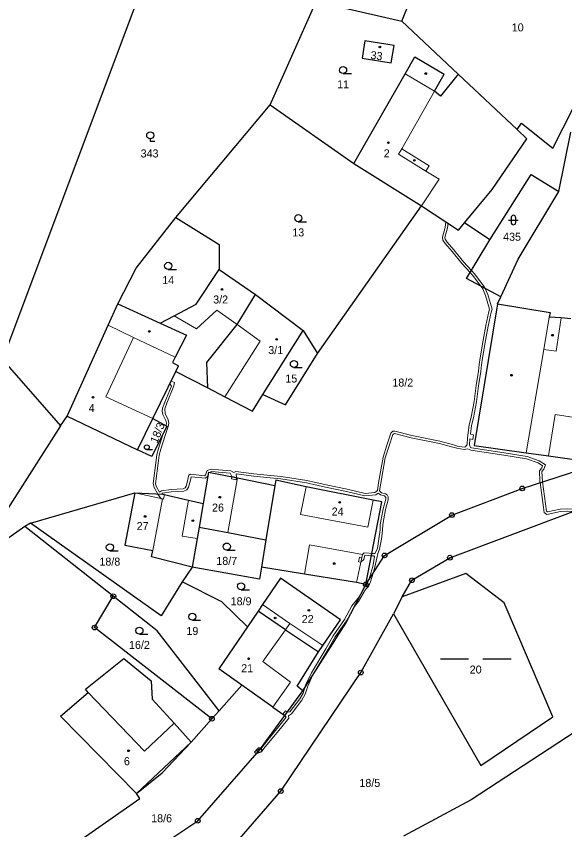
# Model space of a CAD drawing. Extents: x -791548 to -789311, y -1142631 to -1140855.
# Drawn here: x -790444.3 to -790327.9, y -1142288.4 to -1142115.7 of the extents above; entities that cross this region are included whole.
import ezdxf
from ezdxf.enums import TextEntityAlignment as Align

# ---------------------------------------------------------------- set-up
doc = ezdxf.new("R2010")
doc.units = 0
doc.header["$LTSCALE"] = 0.68
for name, color, linetype, lineweight in [('1', 7, 'Continuous', 25), ('13', 7, 'Continuous', 13), ('3', 7, 'Continuous', 25), ('4', 7, 'Continuous', 13), ('5', 7, 'Continuous', 25), ('8', 7, 'Continuous', 25)]:
    doc.layers.add(name, color=color, linetype=linetype, lineweight=lineweight)
doc.layers.add('2', color=7, linetype='Continuous')

msp = doc.modelspace()

# ---------------------------------------------------------------- linework, layer by layer
at = {"layer": '1'}
for p, q in [((-790415.68, -1142104.15), (-790447.27, -1142188.54)), ((-790330.46, -1142143.68), (-790314.29, -1142111.65)), ((-790390.45, -1142134.47), (-790380.65, -1142112.49)), ((-790380.65, -1142112.49), (-790362.5, -1142116.7)), ((-790362.5, -1142116.7), (-790360.74, -1142112.34)), ((-790362.5, -1142116.7), (-790350.55, -1142127.95)), ((-790370.32, -1142120.88), (-790370.91, -1142124.53)), ((-790364.14, -1142121.88), (-790370.32, -1142120.88)), ((-790364.73, -1142125.53), (-790364.14, -1142121.88)), ((-790361.79, -1142127.86), (-790359.72, -1142124.25)), ((-790359.72, -1142124.25), (-790353.52, -1142127.92)), ((-790370.91, -1142124.53), (-790364.73, -1142125.53)), ((-790372.68, -1142146.9), (-790361.79, -1142127.86)), ((-790355.58, -1142131.57), (-790353.52, -1142127.92)), ((-790350.55, -1142127.95), (-790354.27, -1142132.64)), ((-790350.55, -1142127.95), (-790338.04, -1142139.73)), ((-790354.27, -1142132.64), (-790355.58, -1142131.57)), ((-790410.46, -1142158.37), (-790390.45, -1142134.47)), ((-790390.45, -1142134.47), (-790372.68, -1142146.9)), ((-790338.04, -1142139.73), (-790337.12, -1142138.36)), ((-790335.94, -1142141.69), (-790338.04, -1142139.73)), ((-790337.12, -1142138.36), (-790330.46, -1142143.68)), ((-790329.14, -1142152.86), (-790326.62, -1142140.29)), ((-790343.35, -1142152.44), (-790335.94, -1142141.69)), ((-790372.68, -1142146.9), (-790358.3, -1142155.94)), ((-790343.85, -1142163.15), (-790335.03, -1142149.26)), ((-790335.03, -1142149.26), (-790329.14, -1142152.86)), ((-790349.2, -1142159.55), (-790343.35, -1142152.44)), ((-790337.78, -1142167.2), (-790329.14, -1142152.86)), ((-790380.41, -1142187.28), (-790358.3, -1142155.94)), ((-790358.3, -1142155.94), (-790350.46, -1142161.08)), ((-790418.91, -1142169.15), (-790410.46, -1142158.37)), ((-790410.46, -1142158.37), (-790401.23, -1142164.11)), ((-790350.46, -1142161.08), (-790349.2, -1142159.55)), ((-790343.85, -1142163.15), (-790349.2, -1142159.55)), ((-790348.76, -1142171.34), (-790343.85, -1142163.15)), ((-790401.23, -1142164.11), (-790401.29, -1142169.44)), ((-790341.49, -1142175.23), (-790337.78, -1142167.2)), ((-790422.8, -1142176.69), (-790418.91, -1142169.15)), ((-790406.11, -1142176.79), (-790401.29, -1142169.44)), ((-790401.29, -1142169.44), (-790393.58, -1142174.73)), ((-790341.49, -1142175.23), (-790348.76, -1142171.34)), ((-790397.42, -1142181.07), (-790393.58, -1142174.73)), ((-790393.58, -1142174.73), (-790383.43, -1142182.39)), ((-790342.17, -1142176.71), (-790341.49, -1142175.23)), ((-790424.85, -1142181.26), (-790422.8, -1142176.69)), ((-790422.8, -1142176.69), (-790413.8, -1142180.83)), ((-790410.81, -1142179.26), (-790406.11, -1142176.79)), ((-790342.17, -1142176.71), (-790347.13, -1142206.82)), ((-790342.17, -1142176.71), (-790331.02, -1142178.55)), ((-790413.8, -1142180.83), (-790410.81, -1142179.26)), ((-790331.02, -1142178.55), (-790331.19, -1142179.52)), ((-790328.69, -1142179.71), (-790331.19, -1142179.52)), ((-790433.54, -1142200.57), (-790424.85, -1142181.26)), ((-790413.8, -1142180.83), (-790408.2, -1142183.4)), ((-790403.88, -1142189.18), (-790397.42, -1142181.07)), ((-790326.63, -1142179.87), (-790328.69, -1142179.71)), ((-790391.97, -1142195.94), (-790383.43, -1142182.39)), ((-790383.43, -1142182.39), (-790380.41, -1142187.28)), ((-790408.2, -1142183.4), (-790410.6, -1142188.02)), ((-790410.6, -1142188.02), (-790411.2, -1142189.17)), ((-790387.15, -1142198.15), (-790380.41, -1142187.28)), ((-790447.27, -1142188.54), (-790434.91, -1142202.65)), ((-790411.2, -1142189.17), (-790409.88, -1142189.89)), ((-790410.45, -1142191.06), (-790409.88, -1142189.89)), ((-790403.7, -1142194.56), (-790403.88, -1142189.18)), ((-790415.35, -1142201.03), (-790410.45, -1142191.06)), ((-790410.45, -1142191.06), (-790403.7, -1142194.56)), ((-790403.7, -1142194.56), (-790400.06, -1142196.44)), ((-790400.06, -1142196.44), (-790394.2, -1142199.48)), ((-790394.2, -1142199.48), (-790391.97, -1142195.94)), ((-790391.97, -1142195.94), (-790387.15, -1142198.15)), ((-790434.91, -1142202.65), (-790433.54, -1142200.57)), ((-790433.54, -1142200.57), (-790418.62, -1142207.68)), ((-790418.62, -1142207.68), (-790415.35, -1142201.03)), ((-790415.35, -1142201.03), (-790412.38, -1142202.69)), ((-790434.91, -1142202.65), (-790447.12, -1142221.74)), ((-790412.38, -1142202.69), (-790415.55, -1142209.15)), ((-790347.13, -1142206.82), (-790336.11, -1142208.37)), ((-790415.55, -1142209.15), (-790418.62, -1142207.68)), ((-790336.11, -1142208.37), (-790331.39, -1142209)), ((-790331.39, -1142209), (-790297.38, -1142213.8)), ((-790336.95, -1142215.9), (-790324.53, -1142211.91)), ((-790403.5, -1142212.48), (-790404.64, -1142219.08)), ((-790403.5, -1142212.48), (-790397.37, -1142213.63)), ((-790397.37, -1142213.63), (-790389.44, -1142215.31)), ((-790389.44, -1142215.31), (-790391.33, -1142226.82)), ((-790389.23, -1142214.18), (-790389.44, -1142215.31)), ((-790382.81, -1142215.54), (-790389.23, -1142214.18)), ((-790368.61, -1142218.37), (-790382.81, -1142215.54)), ((-790441.28, -1142223.26), (-790419.19, -1142216.86)), ((-790419.19, -1142216.86), (-790421.25, -1142227.97)), ((-790419.19, -1142216.86), (-790413.19, -1142217.16)), ((-790413.19, -1142217.16), (-790407.76, -1142218.38)), ((-790351.87, -1142221.56), (-790336.95, -1142215.9)), ((-790370.14, -1142236.3), (-790366.75, -1142218.74)), ((-790366.75, -1142218.74), (-790368.61, -1142218.37)), ((-790352.29, -1142230.61), (-790326.11, -1142220.77)), ((-790366.17, -1142230.14), (-790351.87, -1142221.56)), ((-790442.51, -1142223.96), (-790460.61, -1142236.7)), ((-790441.28, -1142223.26), (-790442.51, -1142223.96)), ((-790423.73, -1142238.79), (-790442.51, -1142223.96)), ((-790413.55, -1142242.99), (-790441.28, -1142223.26)), ((-790405.52, -1142224.14), (-790405.94, -1142226.57)), ((-790405.52, -1142224.14), (-790399.43, -1142225.29)), ((-790399.43, -1142225.29), (-790391.33, -1142226.82)), ((-790405.94, -1142226.57), (-790406.98, -1142232.61)), ((-790391.33, -1142226.82), (-790392.28, -1142232.62)), ((-790421.25, -1142227.97), (-790415.36, -1142229.07)), ((-790415.61, -1142230.43), (-790415.36, -1142229.07)), ((-790406.98, -1142232.61), (-790415.61, -1142230.43)), ((-790370.14, -1142236.3), (-790366.17, -1142230.14)), ((-790360.35, -1142235.41), (-790352.29, -1142230.61)), ((-790406.98, -1142232.61), (-790409.14, -1142235.72)), ((-790392.72, -1142235.14), (-790406.98, -1142232.61)), ((-790392.28, -1142232.62), (-790392.72, -1142235.14)), ((-790383.13, -1142234.11), (-790392.28, -1142232.62)), ((-790372.09, -1142235.91), (-790383.13, -1142234.11)), ((-790348.92, -1142234), (-790362.42, -1142238.92)), ((-790340.78, -1142240.21), (-790348.92, -1142234)), ((-790409.14, -1142235.72), (-790413.55, -1142242.99)), ((-790400.69, -1142239.95), (-790409.14, -1142235.72)), ((-790388.24, -1142234.94), (-790392.07, -1142240.58)), ((-790375.51, -1142243.78), (-790388.24, -1142234.94)), ((-790374.36, -1142244.52), (-790370.14, -1142236.3)), ((-790370.14, -1142236.3), (-790372.09, -1142235.91)), ((-790362.42, -1142238.92), (-790360.35, -1142235.41)), ((-790427.69, -1142245.45), (-790423.73, -1142238.79)), ((-790414.42, -1142246.14), (-790423.73, -1142238.79)), ((-790395.28, -1142245.29), (-790400.69, -1142239.95)), ((-790362.42, -1142238.92), (-790364.25, -1142242.5)), ((-790392.07, -1142240.58), (-790393, -1142241.95)), ((-790330.43, -1142264.38), (-790340.78, -1142240.21)), ((-790393, -1142241.95), (-790395.28, -1142245.29)), ((-790387.21, -1142245.94), (-790393, -1142241.95)), ((-790371.2, -1142255), (-790364.25, -1142242.5)), ((-790364.25, -1142242.5), (-790345.76, -1142274.76)), ((-790383.5, -1142258.87), (-790374.36, -1142244.52)), ((-790379.28, -1142249.22), (-790375.51, -1142243.78)), ((-790402.79, -1142264.82), (-790427.69, -1142245.45)), ((-790401.26, -1142263.11), (-790414.42, -1142246.14)), ((-790395.28, -1142245.29), (-790401.34, -1142254.22)), ((-790387.21, -1142245.94), (-790380.15, -1142250.62)), ((-790380.15, -1142250.62), (-790379.28, -1142249.22)), ((-790429.63, -1142258.56), (-790421.48, -1142251.99)), ((-790421.48, -1142251.99), (-790415.72, -1142256.74)), ((-790384.72, -1142257.9), (-790380.15, -1142250.62)), ((-790396.42, -1142257.7), (-790401.34, -1142254.22)), ((-790388.19, -1142280.16), (-790371.2, -1142255)), ((-790415.72, -1142256.74), (-790415.45, -1142260.62)), ((-790429.09, -1142259.22), (-790429.63, -1142258.56)), ((-790401.26, -1142263.11), (-790396.42, -1142257.7)), ((-790389.89, -1142262.32), (-790396.42, -1142257.7)), ((-790387.33, -1142264.12), (-790383.5, -1142258.87)), ((-790383.5, -1142258.87), (-790384.72, -1142257.9)), ((-790434.96, -1142264.23), (-790429.09, -1142259.22)), ((-790415.45, -1142260.62), (-790410.82, -1142265.77)), ((-790389.89, -1142262.32), (-790387.33, -1142264.12)), ((-790402.79, -1142264.82), (-790401.26, -1142263.11)), ((-790392.71, -1142271.46), (-790387.33, -1142264.12)), ((-790319.06, -1142263.2), (-790347.8, -1142282.01)), ((-790418.82, -1142280.69), (-790434.96, -1142264.23)), ((-790410.82, -1142265.77), (-790407.22, -1142269.77)), ((-790407.22, -1142269.77), (-790402.79, -1142264.82)), ((-790345.76, -1142274.76), (-790330.43, -1142264.38)), ((-790413.33, -1142276.29), (-790407.22, -1142269.77)), ((-790405.82, -1142286.48), (-790392.71, -1142271.46)), ((-790418.82, -1142280.69), (-790413.33, -1142276.29)), ((-790418.1, -1142281.74), (-790418.82, -1142280.69)), ((-790399.5, -1142293.19), (-790388.19, -1142280.16)), ((-790441.89, -1142298.31), (-790418.1, -1142281.74)), ((-790347.8, -1142282.01), (-790362.11, -1142289.76)), ((-790422.96, -1142297.87), (-790405.82, -1142286.48))]:
    msp.add_line(p, q, dxfattribs=at)
msp.add_lwpolyline([(-790407.76, -1142218.38), (-790404.64, -1142219.08), (-790405.52, -1142224.14)], dxfattribs=at)
at = {"layer": '13'}
for points in [[(-790353.14, -1142159.32), (-790353.32, -1142160.48), (-790353.87, -1142162.57), (-790353.8, -1142163.17), (-790353.3, -1142163.92), (-790351.83, -1142165.6), (-790349.76, -1142168.13), (-790348, -1142170.07), (-790347.73, -1142169.62), (-790349.38, -1142167.81), (-790351.45, -1142165.28), (-790352.9, -1142163.62), (-790353.32, -1142162.99), (-790353.37, -1142162.61), (-790352.82, -1142160.58), (-790352.68, -1142159.62)], [(-790347.73, -1142169.62), (-790348, -1142170.07), (-790347.46, -1142170.66), (-790345.7, -1142172.98), (-790344.8, -1142173.46), (-790344.86, -1142173.32), (-790345.3, -1142172.68), (-790347.08, -1142170.34)], [(-790398.67, -1142213.89), (-790397.69, -1142214.08), (-790397.6, -1142213.59), (-790398.58, -1142213.4)], [(-790332.65, -1142214.52), (-790333.14, -1142214.68), (-790332.28, -1142221), (-790331.71, -1142221.45), (-790328.85, -1142220.82), (-790327.24, -1142220.74), (-790326.11, -1142220.77), (-790319.06, -1142221.21), (-790317.66, -1142221.3), (-790318.89, -1142220.75), (-790321.01, -1142220.53), (-790325.13, -1142220.29), (-790327.24, -1142220.24), (-790328.91, -1142220.32), (-790331.59, -1142220.91), (-790331.82, -1142220.74)], [(-790413.54, -1142218.09), (-790413.3, -1142218.14), (-790413.06, -1142218.19), (-790412.88, -1142217.23), (-790413.19, -1142217.16), (-790414.31, -1142217.1)], [(-790368.96, -1142230.19), (-790368.86, -1142229.69), (-790369.44, -1142229.63), (-790370.51, -1142229.56), (-790370.87, -1142229.91), (-790371.01, -1142230.59), (-790371.5, -1142230.49), (-790371.7, -1142231.47), (-790371.21, -1142231.57), (-790370.54, -1142230.99), (-790370.37, -1142230.09), (-790369.48, -1142230.13)], [(-790368.57, -1142233.87), (-790369.51, -1142235.32), (-790370, -1142236.43), (-790370.46, -1142236.92), (-790371.45, -1142238.85), (-790372.55, -1142241), (-790371.69, -1142239.94), (-790370.23, -1142237.4), (-790369.6, -1142236.75), (-790369.11, -1142235.71)], [(-790383.06, -1142258.18), (-790381.35, -1142255.49), (-790378.2, -1142250.19), (-790376.63, -1142247.43), (-790374.25, -1142244), (-790372.55, -1142241), (-790371.45, -1142238.85), (-790373.08, -1142240.86), (-790374.67, -1142243.74), (-790377.05, -1142247.17), (-790378.64, -1142249.93), (-790381.7, -1142255.06), (-790382.91, -1142257.69)], [(-790381.35, -1142255.49), (-790383.06, -1142258.18), (-790383.44, -1142259.4), (-790384.17, -1142260.55), (-790386.23, -1142263.37), (-790386.81, -1142263.4), (-790387.33, -1142264.12), (-790387.01, -1142264.49), (-790388.66, -1142266.54), (-790390.84, -1142269.19), (-790392.15, -1142270.81), (-790392.71, -1142271.46), (-790393.4, -1142272.25), (-790392.3, -1142271.83), (-790391.75, -1142271.11), (-790390.46, -1142269.51), (-790388.28, -1142266.86), (-790386.49, -1142264.65), (-790386.54, -1142264.18), (-790385.89, -1142263.75), (-790383.75, -1142260.83), (-790382.98, -1142259.62), (-790382.45, -1142257.87)], [(-790387.74, -1142263.83), (-790387.33, -1142264.12), (-790386.81, -1142263.4), (-790387.21, -1142263.11)], [(-790393.12, -1142271.16), (-790393.77, -1142271.92), (-790393.4, -1142272.25), (-790392.71, -1142271.46)]]:
    msp.add_lwpolyline(points, close=True, dxfattribs=at)
for points in [[(-790364.02, -1142204.25), (-790360.51, -1142205.14), (-790354.53, -1142206.36), (-790351.7, -1142207.13), (-790350.82, -1142207.38), (-790349.26, -1142207.67), (-790348.56, -1142207.47), (-790347.85, -1142207.78), (-790340.82, -1142208.84), (-790336.02, -1142209.62), (-790333.54, -1142210.5), (-790332.65, -1142211.1), (-790332.79, -1142211.54), (-790333.27, -1142212.16), (-790333.17, -1142214.44), (-790333.14, -1142214.68), (-790332.65, -1142214.52), (-790332.77, -1142212.32), (-790332.35, -1142211.8), (-790332.01, -1142210.93), (-790333.32, -1142210.04), (-790335.9, -1142209.14), (-790340.74, -1142208.34), (-790347.71, -1142207.3), (-790347.93, -1142207.2), (-790348.13, -1142206.66), (-790348.07, -1142205.39), (-790347.45, -1142205.49), (-790347.29, -1142204.51), (-790347.95, -1142204.4), (-790347.68, -1142202.52), (-790347.28, -1142200.91), (-790346.67, -1142197.54), (-790346.22, -1142194.12), (-790345.74, -1142191.05), (-790345.58, -1142189.68), (-790345.38, -1142188.27), (-790344.74, -1142184.49), (-790344.19, -1142181.44), (-790343.52, -1142178.45), (-790343.32, -1142177.83), (-790344.26, -1142174.75), (-790344.8, -1142173.46), (-790345.7, -1142172.98), (-790345.3, -1142173.56), (-790344.74, -1142174.91), (-790343.86, -1142177.88), (-790344, -1142178.31), (-790344.69, -1142181.34), (-790345.24, -1142184.41), (-790345.88, -1142188.19), (-790346.08, -1142189.62), (-790346.24, -1142190.99), (-790346.72, -1142194.04), (-790347.17, -1142197.46), (-790347.76, -1142200.81), (-790348.18, -1142202.42), (-790348.56, -1142205.13), (-790348.63, -1142206.6), (-790348.95, -1142207.06), (-790349.28, -1142207.15), (-790350.7, -1142206.9), (-790351.56, -1142206.65), (-790354.41, -1142205.88), (-790360.39, -1142204.66), (-790363.98, -1142203.75), (-790364.43, -1142203.78), (-790364.84, -1142204.15), (-790365.67, -1142206.69), (-790366.48, -1142209.28), (-790367.43, -1142214.74), (-790367.69, -1142216.35), (-790368.2, -1142216.76), (-790370.29, -1142216.96), (-790374.13, -1142216.09), (-790378.56, -1142215.17), (-790382.63, -1142214.25), (-790388.08, -1142213.36), (-790390.38, -1142213.16), (-790393.88, -1142212.79), (-790397.76, -1142212.28), (-790398.12, -1142212.53), (-790398.81, -1142212.18), (-790401.4, -1142211.94), (-790402.9, -1142211.8), (-790403.79, -1142212.08), (-790404.13, -1142213.02), (-790404.33, -1142213.21), (-790407.34, -1142212.89), (-790407.7, -1142213.12), (-790407.83, -1142213.59), (-790407.88, -1142214.05), (-790408.24, -1142215.46)], [(-790408.24, -1142215.46), (-790408.46, -1142215.78), (-790408.9, -1142215.97), (-790411.48, -1142216.14), (-790413.51, -1142216.42), (-790413.93, -1142216.67), (-790414.58, -1142215.54), (-790414.75, -1142214.94), (-790414.13, -1142209.96), (-790413.97, -1142208.82), (-790413.64, -1142207.58), (-790412.75, -1142204.7), (-790412.06, -1142202.79), (-790411.94, -1142202.07), (-790412.08, -1142201.32), (-790412.72, -1142200), (-790412.8, -1142199), (-790412.35, -1142197.78), (-790410.85, -1142194.14), (-790410.74, -1142193.45), (-790411.46, -1142193.12), (-790411.72, -1142193.65), (-790411.41, -1142194.18), (-790412.81, -1142197.6), (-790413.28, -1142198.88), (-790413.36, -1142199.53), (-790413.2, -1142200.18), (-790412.56, -1142201.48), (-790412.44, -1142202.07), (-790412.53, -1142202.61), (-790412.38, -1142202.69), (-790413.12, -1142204.21), (-790414.12, -1142207.44), (-790414.47, -1142208.72), (-790414.63, -1142209.9), (-790415.28, -1142214.88), (-790415.04, -1142215.72), (-790414.31, -1142217.1), (-790413.19, -1142217.16), (-790413.35, -1142216.9), (-790411.42, -1142216.64), (-790408.78, -1142216.47), (-790408.12, -1142216.18), (-790407.78, -1142215.66), (-790407.38, -1142214.15), (-790407.22, -1142213.41), (-790404.15, -1142213.73), (-790403.63, -1142213.23), (-790403.5, -1142212.48), (-790403.38, -1142212.5), (-790402.84, -1142212.3), (-790401.44, -1142212.44), (-790398.95, -1142212.66), (-790398.58, -1142213.4), (-790397.6, -1142213.59), (-790397.64, -1142212.8), (-790393.94, -1142213.29), (-790390.42, -1142213.66), (-790388.14, -1142213.86), (-790382.73, -1142214.75), (-790378.66, -1142215.65), (-790374.23, -1142216.57), (-790370.33, -1142217.46), (-790368.04, -1142217.24), (-790367.52, -1142216.92), (-790367.05, -1142217.29), (-790366.18, -1142217.48), (-790365.86, -1142217.8), (-790365.88, -1142218.22), (-790366.44, -1142220.26), (-790367.06, -1142223.53), (-790367.1, -1142224.72), (-790367.34, -1142226.58), (-790367.68, -1142228.64), (-790368.2, -1142229.73), (-790368.86, -1142229.69), (-790368.96, -1142230.19), (-790368.46, -1142230.24), (-790368.26, -1142230.45), (-790368.68, -1142232.47), (-790369.51, -1142235.32), (-790368.57, -1142233.87), (-790368.2, -1142232.59), (-790367.79, -1142230.71), (-790367.62, -1142229.69), (-790367.2, -1142228.8), (-790366.84, -1142226.66), (-790366.6, -1142224.76), (-790366.56, -1142223.59), (-790365.96, -1142220.38), (-790365.38, -1142218.3), (-790365.36, -1142217.68), (-790365.58, -1142217.29), (-790365.98, -1142217.02), (-790366.83, -1142216.83), (-790367.2, -1142216.42), (-790366.93, -1142214.82), (-790366, -1142209.4), (-790365.19, -1142206.85), (-790364.4, -1142204.43), (-790364.02, -1142204.25)]]:
    msp.add_lwpolyline(points, dxfattribs=at)
at = {"layer": '3'}
for p, q in [((-790374.953, -1142127.83), (-790373.203, -1142127.83)), ((-790339.321, -1142158.421), (-790339.321, -1142159.422)), ((-790338.319, -1142159.422), (-790338.319, -1142158.421)), ((-790384.473, -1142159.27), (-790382.723, -1142159.27)), ((-790339.821, -1142158.921), (-790337.819, -1142158.921)), ((-790412.083, -1142169.4), (-790410.333, -1142169.4)), ((-790385.403, -1142190.23), (-790383.653, -1142190.23)), ((-790416.615, -1142207.66), (-790415.443, -1142207.66)), ((-790424.463, -1142229.16), (-790422.713, -1142229.16)), ((-790399.643, -1142229), (-790397.893, -1142229)), ((-790396.603, -1142237.43), (-790394.853, -1142237.43)), ((-790406.943, -1142243.89), (-790405.193, -1142243.89)), ((-790418.183, -1142246.85), (-790416.433, -1142246.85)), ((-790354.309, -1142252.08), (-790348.309, -1142252.08)), ((-790345.309, -1142252.08), (-790339.309, -1142252.08))]:
    msp.add_line(p, q, dxfattribs=at)
msp.add_lwpolyline([(-790415.89, -1142141.682), (-790415.89, -1142142.18), (-790414.889, -1142142.18)], dxfattribs=at)
for centre, radius in [((-790374.9529, -1142127.0798), 0.75), ((-790415.8893, -1142140.9309), 0.75), ((-790384.4729, -1142158.5198), 0.75), ((-790412.0829, -1142168.6498), 0.75), ((-790385.4029, -1142189.4798), 0.75), ((-790416.6152, -1142207.1574), 0.5025), ((-790424.4629, -1142228.4098), 0.75), ((-790399.6429, -1142228.2498), 0.75), ((-790396.6029, -1142236.6798), 0.75), ((-790406.9429, -1142243.1398), 0.75), ((-790418.1829, -1142246.0998), 0.75)]:
    msp.add_circle(centre, radius, dxfattribs=at)
for centre, start, end in [((-790338.82, -1142158.4209), 0, 180), ((-790338.82, -1142159.4209), 180, 359.98789)]:
    msp.add_arc(centre, 0.5, start, end, dxfattribs=at)
at = {"layer": '4'}
for p, q in [((-790361.79, -1142127.86), (-790355.58, -1142131.57)), ((-790355.58, -1142131.57), (-790362.51, -1142143.82)), ((-790362.51, -1142143.82), (-790363.17, -1142144.97)), ((-790363.17, -1142144.97), (-790357.37, -1142148.54)), ((-790362.51, -1142143.82), (-790356.68, -1142147.41)), ((-790356.68, -1142147.41), (-790357.37, -1142148.54)), ((-790357.37, -1142148.54), (-790354.59, -1142150.25)), ((-790354.59, -1142150.25), (-790358.3, -1142155.94)), ((-790406.07, -1142182.01), (-790410.81, -1142179.26)), ((-790401.79, -1142178.07), (-790406.07, -1142182.01)), ((-790397.42, -1142181.07), (-790401.79, -1142178.07)), ((-790331.19, -1142179.52), (-790332.36, -1142186.39)), ((-790419.48, -1142183.83), (-790424.85, -1142181.26)), ((-790392.56, -1142184.61), (-790397.42, -1142181.07)), ((-790328.69, -1142179.71), (-790329.74, -1142186.74)), ((-790425.3, -1142196.46), (-790419.48, -1142183.83)), ((-790410.6, -1142188.02), (-790419.48, -1142183.83)), ((-790400.06, -1142196.44), (-790392.56, -1142184.61)), ((-790332.36, -1142186.39), (-790336.11, -1142208.37)), ((-790329.74, -1142186.74), (-790332.36, -1142186.39)), ((-790415.35, -1142201.03), (-790425.3, -1142196.46)), ((-790331.39, -1142209), (-790329.97, -1142200.24)), ((-790329.97, -1142200.24), (-790290.68, -1142205.92)), ((-790399.43, -1142225.29), (-790397.37, -1142213.63)), ((-790382.81, -1142215.54), (-790383.98, -1142221.42)), ((-790419.19, -1142216.86), (-790413.3, -1142218.14)), ((-790413.3, -1142218.14), (-790415.36, -1142229.07)), ((-790409.09, -1142226.02), (-790407.76, -1142218.38)), ((-790369.74, -1142224.13), (-790368.61, -1142218.37)), ((-790383.98, -1142221.42), (-790369.74, -1142224.13)), ((-790405.94, -1142226.57), (-790409.09, -1142226.02)), ((-790382.1, -1142227.91), (-790383.13, -1142234.11)), ((-790370.87, -1142229.91), (-790382.1, -1142227.91)), ((-790372.09, -1142235.91), (-790370.87, -1142229.91)), ((-790386.26, -1142244.55), (-790392.07, -1142240.58)), ((-790387.21, -1142245.94), (-790386.26, -1142244.55)), ((-790386.26, -1142244.55), (-790379.28, -1142249.22)), ((-790387.21, -1142245.94), (-790392.01, -1142252.68)), ((-790392.01, -1142252.68), (-790386.09, -1142257.06)), ((-790386.09, -1142257.06), (-790389.89, -1142262.32)), ((-790429.09, -1142259.22), (-790417.12, -1142271.67)), ((-790417.12, -1142271.67), (-790410.82, -1142265.77)), ((-790418.82, -1142280.69), (-790407.22, -1142269.77))]:
    msp.add_line(p, q, dxfattribs=at)
at = {"layer": '5'}
for centre in [(-790367.1588, -1142122.1733), (-790357.4088, -1142127.8133), (-790365.3488, -1142142.5033), (-790359.8568, -1142146.2592), (-790400.6788, -1142173.6633), (-790416.0988, -1142182.5833), (-790389.0488, -1142184.2533), (-790330.5288, -1142183.3833), (-790339.2088, -1142191.8633), (-790428.0288, -1142196.5433), (-790401.1288, -1142217.7733), (-790375.6788, -1142218.8533), (-790416.9788, -1142221.8533), (-790406.8488, -1142222.7433), (-790376.8388, -1142231.8533), (-790382.2188, -1142241.7833), (-790389.3888, -1142243.4033), (-790395.0088, -1142252.0833), (-790420.4988, -1142271.6133)]:
    msp.add_circle(centre, 0.175, dxfattribs=at)
at = {"layer": '8'}
for centre, radius in [((-790336.9499, -1142215.9), 0.5), ((-790336.9499, -1142215.9), 0.0303), ((-790351.8699, -1142221.56), 0.5), ((-790351.8699, -1142221.56), 0.0303), ((-790366.1699, -1142230.14), 0.5), ((-790366.1699, -1142230.14), 0.0303), ((-790352.2899, -1142230.61), 0.5), ((-790352.2899, -1142230.61), 0.0303), ((-790370.1399, -1142236.3), 0.5), ((-790370.1399, -1142236.3), 0.0303), ((-790360.3499, -1142235.41), 0.5), ((-790360.3499, -1142235.41), 0.0303), ((-790423.73, -1142238.7899), 0.5), ((-790423.73, -1142238.7899), 0.0303), ((-790427.69, -1142245.4499), 0.5), ((-790427.69, -1142245.4499), 0.0303), ((-790371.1999, -1142255), 0.5), ((-790371.1999, -1142255), 0.0303), ((-790402.79, -1142264.8199), 0.5), ((-790402.79, -1142264.8199), 0.0303), ((-790392.7099, -1142271.46), 0.5), ((-790392.7099, -1142271.46), 0.0303), ((-790388.1899, -1142280.16), 0.5), ((-790388.1899, -1142280.16), 0.0303), ((-790405.8199, -1142286.48), 0.5), ((-790405.8199, -1142286.48), 0.0303)]:
    msp.add_circle(centre, radius, dxfattribs=at)

# ---------------------------------------------------------------- texts
at = {"layer": '2'}
for s, p in [('10', (-790337.899, -1142118.872)), ('11', (-790374.959, -1142130.962)), ('343', (-790416.039, -1142145.632)), ('2', (-790365.71, -1142145.612)), ('13', (-790384.479, -1142162.402)), ('435', (-790339.099, -1142163.322)), ('14', (-790412.089, -1142172.532)), ('3/2', (-790400.95, -1142176.642)), ('3/1', (-790389.26, -1142187.382)), ('15', (-790385.949, -1142193.422)), ('18/2', (-790362.289, -1142194.282)), ('4', (-790428.33, -1142199.702)), ('26', (-790401.509, -1142220.822)), ('24', (-790376.119, -1142221.662)), ('27', (-790417.509, -1142224.742)), ('18/8', (-790424.469, -1142232.292)), ('18/7', (-790399.649, -1142232.132)), ('18/9', (-790396.609, -1142240.712)), ('22', (-790382.479, -1142244.492)), ('19', (-790406.949, -1142247.022)), ('16/2', (-790418.189, -1142249.982)), ('21', (-790395.319, -1142254.932)), ('20', (-790346.819, -1142255.212)), ('6', (-790420.85, -1142274.672)), ('18/5', (-790369.289, -1142279.282)), ('18/6', (-790413.479, -1142286.792))]:
    msp.add_text(s, height=1.7, dxfattribs=at).set_placement(p, align=Align.CENTER)
for s, rotation, p in [('33', 353, (-790367.9626, -1142124.8592)), ('18/3', 68, (-790413.5841, -1142204.4074))]:
    msp.add_text(s, height=1.7, rotation=rotation, dxfattribs=at).set_placement(p, align=Align.CENTER)

doc.saveas('drawing.dxf')
